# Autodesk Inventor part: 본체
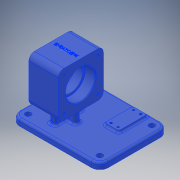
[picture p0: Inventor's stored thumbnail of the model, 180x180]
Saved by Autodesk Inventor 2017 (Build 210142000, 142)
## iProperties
Created: 2019-09
Part Number: 본체
Material: 알루미늄 6061
Document SubType Name: Modeling
Designer: mduedu
Density: 2.71 g/cm^3
Appearance: 기본값
Mass: 636.364 g
Surface Area: 520.125 cm^2
Volume: 234.821 cm^3
Author: mduedu
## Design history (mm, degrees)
sketch "스케치1"
  geometry: L1 (42, -62)-(-84, -62); L2 (-84, -62)-(-84, 36); L3 (-84, 36)-(42, 36); L4 (42, 36)-(42, -62); 1 further point
  constraints: 8 end point, 2 parallel, 1 horizontal, 1 perpendicular
  dimensions: "d0" = 36 distance from line of L3 point (0, 0); "d1" = 98 distance of L1.end L2.end; "d2" = 42 distance from line of L4 point (0, 0); "d3" = 126 distance of L2.end L3.end
extrude "돌출1" new body sketch "스케치1" distance "d4" = 9; taper "d5" = 0 deg
sketch "스케치2"
  geometry: L1 (0, -62)-(0, 36) reference; L2 (27, -32)-(91, -32); L3 (91, -32)-(91, 32); L4 (91, 32)-(27, 32); L5 (27, 32)-(27, -32); L6 (27, -32)-(91, 32); L7 (91, -32)-(27, 32); 3 further points
  constraints: 12 end point, 3 midpoint, 2 parallel, 1 horizontal, 1 horizontal alignment, 1 perpendicular
  dimensions: "d87" = 64 distance of L4.end L3.end; "d88" = 64 distance of L3.end L2.end; "d89" = 59 distance from line of point (59, 0) L1
extrude "돌출2" join sketch "스케치2" stored distance "d8" = 42; taper "d9" = 0 deg
sketch "스케치3"
  geometry: L1 (-17, 4)-(17, 4); L2 (17, 4)-(17, -4); L3 (17, -4)-(-17, -4); L4 (-17, -4)-(-17, 4); L5 (-4, 20)-(4, 20); L6 (4, 20)-(4, -20); L7 (4, -20)-(-4, -20); L8 (-4, -20)-(-4, 20); 5 further points
  constraints: 16 end point, 4 midpoint, 4 parallel, 2 horizontal, 2 horizontal alignment, 2 perpendicular, 2 vertical alignment
  dimensions: "d10" = 8 distance of L5.start L5.end; "d12" = 8 distance of L1.end L2.end; "d13" = 34 distance of L2.end L3.end; "d14" = 40 distance of L5.end L6.end
extrude "돌출3" join sketch "스케치3" stored distance "d15" = 42; taper "d16" = 0 deg
sketch "스케치4"
  geometry: L1 (-32, 91)-(-32, 27) reference; L2 (32, 91)-(-32, 91) reference; L3 (32, 27)-(32, 91) reference; L4 (-32, 27)-(32, 27) reference; C1 r 21 at (0, 59); 3 further points
  constraints: 2 midpoint, 1 centre point, 1 horizontal alignment, 1 vertical alignment
  dimensions: "d17" = 42 diameter of C1
extrude "돌출4" cut sketch "스케치4" distance "d18" = 15; taper "d19" = 0 deg
hole "구멍1" diameter "d22" = 36; stored, may be unused: countersink angle "d26" = 90 deg, drill point angle "d28" = 118 deg; dims "d20" = 10, "d21" = 10, "d23" = 6, "d24" = 4, "d25" = 2, "d27" = 8
fillet "모깎기1" dims "d29" = 0.3
chamfer "모따기1" distance "d30" = 1; stored, may be unused: second distance "d31" = 2, angle "d32" = 45 deg
fillet "모깎기9" dims "d90" = 8
sketch "스케치11"
  geometry: L1 (-24, 27)-(24, 27) reference; L2 (32, 35)-(32, 83) reference; L3 (24, 91)-(-24, 91) reference; L4 (-32, 83)-(-32, 35) reference; C1 r 22 at (0, 59) reference; A1 r 8 centre (-24, 35) between (-32, 35) and (-24, 27) reference; A2 r 8 centre (24, 35) between (24, 27) and (32, 35) reference; A3 r 8 centre (24, 83) between (32, 83) and (24, 91) reference; A4 r 8 centre (-24, 83) between (-24, 91) and (-32, 83) reference; 5 further points
  constraints: 4 coincident
hole "구멍6" sketch "스케치11" at (-24, 83), (24, 83), (24, 35), (-24, 35) diameter "d91" = 3.242; stored, may be unused: countersink angle "d95" = 90 deg, drill point angle "d97" = 118 deg; dims "d92" = 8, "d93" = 4, "d94" = 2, "d96" = 10
fillet "모깎기2" dims "d44" = 12
sketch "스케치6"
  geometry: L1 (-42, 50)-(-42, -24) reference; L2 (-30, -36)-(72, -36) reference; L3 (84, -24)-(84, 50) reference; L4 (72, 62)-(-30, 62) reference; L5 (17, 4)-(17, -4) reference; L6 (17, -4)-(4, -4) reference; L7 (4, -4)-(4, -20) reference; L8 (4, -20)-(-4, -20) reference; L9 (-4, -20)-(-4, -4) reference; L10 (-4, -4)-(-17, -4) reference; L11 (-17, -4)-(-17, 4) reference; L12 (-17, 4)-(-4, 4) reference; L13 (-4, 4)-(-4, 20) reference; L14 (-4, 20)-(4, 20) reference; L15 (4, 20)-(4, 4) reference; L16 (4, 4)-(17, 4) reference; A1 r 12 centre (-30, 50) between (-30, 62) and (-42, 50) reference; A2 r 12 centre (-30, -24) between (-42, -24) and (-30, -36) reference; A3 r 12 centre (72, -24) between (72, -36) and (84, -24) reference; A4 r 12 centre (72, 50) between (84, 50) and (72, 62) reference; 5 further points
  constraints: 4 coincident
hole "구멍3" sketch "스케치6" at (-30, 50), (72, 50), (72, -24), (-30, -24) diameter "d45" = 8; stored, may be unused: countersink angle "d49" = 90 deg, drill point angle "d51" = 118 deg; dims "d46" = 8, "d47" = 4, "d48" = 2, "d50" = 10
sketch "스케치7"
  geometry: L1 (38, 57)-(58, 57); L2 (58, 57)-(58, 17); L3 (58, 17)-(38, 17); L4 (38, 17)-(38, 57); L5 (72, 62)-(-30, 62) reference; 3 further points
  constraints: 8 end point, 2 midpoint, 2 parallel, 1 horizontal, 1 perpendicular
  dimensions: "d52" = 48 horizontal distance of point (48, 57) point (0, 0); "d53" = 20 distance of L1.start L1.end; "d54" = 40 distance of L1.end L2.end; "d55" = 25 distance from line of point (38, 37) L5
extrude "돌출5" join sketch "스케치7" distance "d56" = 3; taper "d57" = 0 deg
fillet "모깎기3" dims "d58" = 3
fillet "모깎기4" dims "d59" = 3
fillet "모깎기5" dims "d60" = 3
fillet "모깎기6" dims "d61" = 3
fillet "모깎기7" dims "d62" = 3
fillet "모깎기8" dims "d63" = 3
sketch "스케치8"
  geometry: L1 (72, 62)-(58.317, 62) reference; L2 (84, -24)-(84, 50) reference; C1 r 1.5 at (43, 53); C2 r 1.5 at (53, 21); 1 further point
  constraints: 2 centre point, 1 equal radius
  dimensions: "d64" = 3 diameter of C1; "d65" = 9 distance from line of C1.centre L1; "d66" = 32 vertical distance of C2.centre C1.centre; "d67" = 10 horizontal distance of C2.centre C1.centre; "d68" = 31 distance from line of L2 C2.centre
hole "구멍4" sketch "스케치8" at (43, 53), (53, 21) diameter "d69" = 3; stored, may be unused: countersink angle "d73" = 90 deg, drill point angle "d75" = 118 deg; dims "d70" = 8, "d71" = 4, "d72" = 2, "d74" = 6
sketch "스케치9"
  geometry: C1 r 1.5 at (43, 53) reference; C2 r 1.5 at (53, 21) reference; 3 further points
  constraints: 2 horizontal alignment, 2 vertical alignment
hole "구멍5" sketch "스케치9" at (53, 53), (43, 21) diameter "d76" = 3.242; stored, may be unused: countersink angle "d80" = 90 deg, drill point angle "d82" = 118 deg; dims "d77" = 6, "d78" = 4, "d79" = 2, "d81" = 8
sketch "스케치10"
  geometry: 2 further points
  constraints: 1 coincident, 1 other
feature "엠보싱1" sketch "스케치10" dims "d0" = 36, "d1" = 98, "d2" = 42, "d3" = 126, "d12" = 8, "d13" = 34, "d85" = 0.5, "d86" = 0
node "솔리드1"
mirror "대칭1"
mirror "대칭2"
node "투영된 루프1"
node "투영된 루프2"
